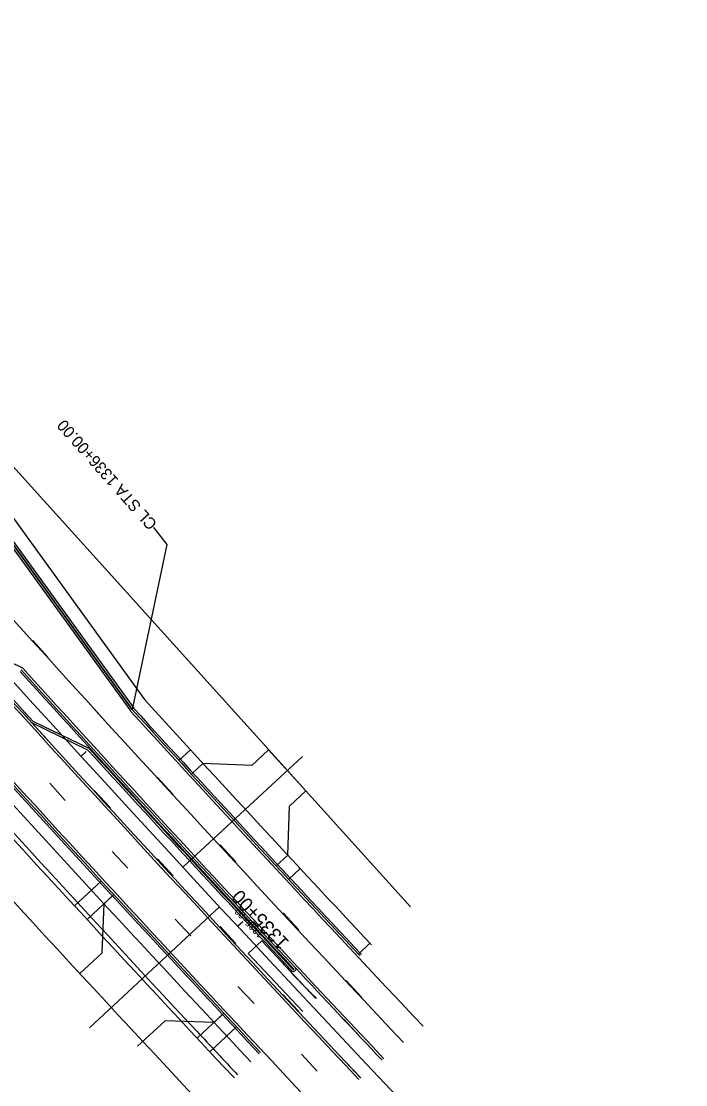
# Model space of a CAD drawing. Extents: x 2252205 to 2259955, y 13788514 to 13798103.
# Drawn here: x 2256634 to 2256921.6, y 13791797 to 13792257 of the extents above; entities that cross this region are included whole.
import ezdxf

# ---------------------------------------------------------------- set-up
doc = ezdxf.new("R2010")
doc.units = 0
for name, color, linetype in [('D_RDWY_TRACK_P_AND_T', 7, 'Continuous'), ('GEOM_CENTERLINE_ALIGN', 7, 'Continuous'), ('GEOM_CENTERLINE_STA_100', 7, 'Continuous'), ('GEOM_CENTERLINE_STA_50', 7, 'Continuous'), ('ROAD_BIKE_SHARED_USE', 7, 'Continuous'), ('Road_Curb_Back', 7, 'Continuous'), ('Road_Curb_Face', 7, 'Continuous'), ('ROAD_DRIVEWAY_EP', 7, 'Continuous'), ('Road_EdgeOfPavementInside', 7, 'Continuous'), ('Road_EdgeOfPavementOutside', 7, 'Continuous'), ('ROAD_PAVMRK_Y_4IN_BRK', 7, 'Continuous'), ('ROAD_ROW_EXIST', 7, 'Continuous'), ('ROAD_ROW_PROPOSED', 7, 'Continuous'), ('ROAD_SCRATCH_DRIVE_CL', 7, 'Continuous'), ('ROAD_SCRATCH_EP_CONTROL', 7, 'Continuous'), ('Road_Sidewalk_Back', 7, 'Continuous'), ('TRAF_PAVMRK_W_4IN_BRK', 7, 'Continuous'), ('TRAF_PAVMRK_W_4IN_SLD', 7, 'Continuous'), ('TRAF_PAVMRK_Y_4IN_SLD', 7, 'Continuous')]:
    doc.layers.add(name, color=color, linetype=linetype)

msp = doc.modelspace()

# ---------------------------------------------------------------- linework, layer by layer
at = {"layer": 'D_RDWY_TRACK_P_AND_T'}
for points in [[(2256761.55, 13791834.26), (2256738.1, 13791859.22), (2256732.27, 13791853.75), (2256755.81, 13791828.68)], [(2256746.32, 13791850.48), (2256747, 13791849.75), (2256747.69, 13791849.01), (2256748.37, 13791848.28), (2256749.05, 13791847.55), (2256749.73, 13791846.81), (2256750.4, 13791846.08), (2256751.08, 13791845.35), (2256751.75, 13791844.63), (2256752.41, 13791843.91), (2256753.08, 13791843.19), (2256753.74, 13791842.48), (2256754.4, 13791841.78), (2256755.06, 13791841.08), (2256755.72, 13791840.39), (2256756.38, 13791839.7), (2256757.04, 13791839.03), (2256757.7, 13791838.37), (2256758.36, 13791837.71), (2256759.02, 13791837.07), (2256759.68, 13791836.44), (2256760.34, 13791835.82), (2256761, 13791835.22), (2256761.67, 13791834.62), (2256761.8, 13791834.5)]]:
    msp.add_lwpolyline(points, dxfattribs=at)
at = {"layer": 'GEOM_CENTERLINE_ALIGN'}
msp.add_arc((2265119, 13799669.27), 11459.16, 219.418553, 224.327385, dxfattribs=at)
at = {"layer": 'GEOM_CENTERLINE_STA_100'}
for p, q in [((2256659.87, 13791939.1), (2256662.09, 13791941.13)), ((2256727.65, 13791865.58), (2256729.85, 13791867.62))]:
    msp.add_line(p, q, dxfattribs=at)
at = {"layer": 'GEOM_CENTERLINE_STA_50'}
for p, q in [((2256659.87, 13791939.1), (2256660.98, 13791940.11)), ((2256727.65, 13791865.58), (2256728.75, 13791866.6))]:
    msp.add_line(p, q, dxfattribs=at)
at = {"layer": 'ROAD_BIKE_SHARED_USE'}
for p, q in [((2256657.07, 13791874.35), (2256668.66, 13791885.11)), ((2256662.52, 13791868.49), (2256674.1, 13791879.24)), ((2256710.13, 13791817.18), (2256721.74, 13791827.95)), ((2256715.58, 13791811.32), (2256727.18, 13791822.09))]:
    msp.add_line(p, q, dxfattribs=at)
for radius, start, end in [(11494.99, 220.925074, 223.155573), (11504.99, 220.928174, 223.15647)]:
    msp.add_arc((2265119, 13799669.27), radius, start, end, dxfattribs=at)
at = {"layer": 'Road_Curb_Back'}
for p, q in [((2256623.89, 13792041.13), (2256682.66, 13791959.87)), ((2256663.33, 13791942.48), (2256639.1, 13791954.21))]:
    msp.add_line(p, q, dxfattribs=at)
for centre, radius, start, end in [((2265119, 13799669.27), 11464.33, 220.621764, 222.296129), ((2265119, 13799669.27), 11489.99, 220.923263, 223.155124), ((2265119, 13799669.27), 11453.99, 222.197552, 223.071947), ((2265119, 13799669.27), 11428.33, 222.421868, 223.149555), ((2265119, 13799669.27), 11454.33, 222.421067, 223.071947), ((2256751.77, 13791847.04), 0.167, 223.222, 42.9219)]:
    msp.add_arc(centre, radius, start, end, dxfattribs=at)
at = {"layer": 'Road_Curb_Face'}
msp.add_line((2256623.24, 13792040.61), (2256682.02, 13791959.34), dxfattribs=at)
for radius, start, end in [(11489.16, 220.923263, 223.155049), (11429.16, 222.421868, 223.149631)]:
    msp.add_arc((2265119, 13799669.27), radius, start, end, dxfattribs=at)
at = {"layer": 'ROAD_DRIVEWAY_EP'}
for p, q in [((2256707.23, 13791941.91), (2256702.21, 13791937.27)), ((2256741.07, 13791941.87), (2256733.84, 13791935.18)), ((2256757.22, 13791924.12), (2256741.07, 13791941.87)), ((2256712.66, 13791936.03), (2256707.64, 13791931.39)), ((2256733.84, 13791935.18), (2256712.66, 13791936.03)), ((2256757.22, 13791924.12), (2256750.13, 13791917.56)), ((2256749.31, 13791896.38), (2256750.13, 13791917.56)), ((2256749.31, 13791896.38), (2256744.29, 13791891.74)), ((2256754.74, 13791890.5), (2256749.72, 13791885.86)), ((2256669.83, 13791875.28), (2256674.1, 13791879.24)), ((2256669.01, 13791854.05), (2256669.83, 13791875.28)), ((2256784.9, 13791858.2), (2256779.92, 13791853.51)), ((2256659.34, 13791845.08), (2256669.01, 13791854.05)), ((2256717.44, 13791823.97), (2256721.72, 13791827.94)), ((2256684.38, 13791813.74), (2256696.22, 13791824.73)), ((2256717.44, 13791823.97), (2256696.22, 13791824.73))]:
    msp.add_line(p, q, dxfattribs=at)
at = {"layer": 'Road_EdgeOfPavementInside'}
msp.add_line((2256662.82, 13791941.8), (2256638.6, 13791953.53), dxfattribs=at)
for centre, radius, start, end in [((2265119, 13799669.27), 11465.16, 220.621764, 222.296933), ((2265119, 13799669.27), 11453.16, 222.19675, 223.071947), ((2265119, 13799669.27), 11455.16, 222.421868, 223.071947), ((2256751.77, 13791847.04), 1, 223.222, 42.9219)]:
    msp.add_arc(centre, radius, start, end, dxfattribs=at)
at = {"layer": 'Road_EdgeOfPavementOutside'}
msp.add_line((2256682.02, 13791959.34), (2256623.24, 13792040.61), dxfattribs=at)
for radius, start, end in [(11489.16, 220.923263, 223.155049), (11429.16, 222.421868, 223.149631)]:
    msp.add_arc((2265119, 13799669.27), radius, start, end, dxfattribs=at)
at = {"layer": 'ROAD_PAVMRK_Y_4IN_BRK'}
for points in [[(2256638.6, 13791953.53), (2256645.39, 13791946.19)], [(2256665.76, 13791924.17), (2256665.77, 13791924.16)], [(2256665.77, 13791924.16), (2256672.56, 13791916.82)], [(2256692.93, 13791894.8), (2256692.94, 13791894.79)], [(2256692.94, 13791894.79), (2256699.73, 13791887.45)], [(2256720.11, 13791865.43), (2256720.11, 13791865.42)], [(2256720.11, 13791865.42), (2256726.9, 13791858.08)], [(2256752.88, 13791847.32), (2256752.5, 13791847.72)], [(2256752.89, 13791847.31), (2256752.88, 13791847.32)], [(2256747.28, 13791836.06), (2256747.28, 13791836.05)], [(2256747.28, 13791836.05), (2256754.08, 13791828.71)], [(2256780.31, 13791818.18), (2256773.46, 13791825.47)], [(2256780.32, 13791818.18), (2256780.31, 13791818.18)], [(2256774.53, 13791806.77), (2256774.53, 13791806.76)], [(2256774.53, 13791806.76), (2256780.93, 13791800.01)]]:
    msp.add_lwpolyline(points, dxfattribs=at)
for radius, start, end in [(11465.16, 222.296933, 223.343138), (11453.16, 223.071933, 223.347169)]:
    msp.add_arc((2265119, 13799669.27), radius, start, end, dxfattribs=at)
at = {"layer": 'ROAD_ROW_EXIST'}
msp.add_line((2256429.73, 13792286.64), (2256802.4, 13791873.96), dxfattribs=at)
for start, end in [(220.760702, 223.023397), (223.023397, 223.152425)]:
    msp.add_arc((2265124.02, 13799672.91), 11509.2, start, end, dxfattribs=at)
at = {"layer": 'ROAD_ROW_PROPOSED'}
msp.add_arc((2265116.03, 13799666.59), 11519.16, 220.67779, 223.158467, dxfattribs=at)
at = {"layer": 'ROAD_SCRATCH_DRIVE_CL'}
for p, q in [((2256755.67, 13791939.02), (2256703.91, 13791891.18)), ((2256663.54, 13791821.69), (2256719.86, 13791873.96))]:
    msp.add_line(p, q, dxfattribs=at)
at = {"layer": 'ROAD_SCRATCH_EP_CONTROL'}
msp.add_lwpolyline([(2256691.25, 13792038.09), (2256697.06, 13792030.65), (2256682.02, 13791959.34)], dxfattribs=at)
at = {"layer": 'Road_Sidewalk_Back'}
msp.add_line((2256628.57, 13792044.9), (2256687.32, 13791963.66), dxfattribs=at)
msp.add_arc((2265119, 13799669.27), 11422.33, 222.423828, 223.14901, dxfattribs=at)
at = {"layer": 'TRAF_PAVMRK_W_4IN_BRK'}
for points in [[(2256645.7, 13791981.79), (2256639.02, 13791989.23)], [(2256645.7, 13791981.78), (2256645.7, 13791981.79)], [(2256672.45, 13791952.03), (2256671.66, 13791952.89), (2256665.75, 13791959.46)], [(2256672.46, 13791952.03), (2256672.45, 13791952.03)], [(2256699.68, 13791922.72), (2256692.87, 13791930.05)], [(2256646.34, 13791927.48), (2256646.35, 13791927.47)], [(2256646.35, 13791927.47), (2256653.05, 13791920.04)], [(2256699.69, 13791922.71), (2256699.68, 13791922.72)], [(2256726.91, 13791893.41), (2256720.1, 13791900.73)], [(2256673.35, 13791897.96), (2256673.36, 13791897.95)], [(2256673.36, 13791897.95), (2256680.18, 13791890.64)], [(2256726.92, 13791893.4), (2256726.91, 13791893.41)], [(2256700.64, 13791868.7), (2256700.65, 13791868.7)], [(2256700.65, 13791868.7), (2256707.47, 13791861.38)], [(2256754.14, 13791864.09), (2256747.33, 13791871.42)], [(2256754.15, 13791864.09), (2256754.14, 13791864.09)], [(2256781.37, 13791834.78), (2256774.56, 13791842.11)], [(2256727.94, 13791839.45), (2256727.94, 13791839.44)], [(2256727.94, 13791839.44), (2256734.77, 13791832.13)], [(2256781.38, 13791834.77), (2256781.37, 13791834.78)], [(2256755.23, 13791810.19), (2256755.24, 13791810.19)], [(2256755.24, 13791810.19), (2256762.06, 13791802.87)]]:
    msp.add_lwpolyline(points, dxfattribs=at)
msp.add_arc((2265119, 13799669.27), 11441.16, 220.646831, 223.351209, dxfattribs=at)
at = {"layer": 'TRAF_PAVMRK_W_4IN_SLD'}
msp.add_line((2256622.46, 13792039.98), (2256681.24, 13791958.71), dxfattribs=at)
for radius, start, end in [(11488.16, 220.923263, 223.335434), (11430.16, 222.421868, 223.35492)]:
    msp.add_arc((2265119, 13799669.27), radius, start, end, dxfattribs=at)
at = {"layer": 'TRAF_PAVMRK_Y_4IN_SLD'}
msp.add_line((2256634.62, 13791977.24), (2256610.47, 13791989.03), dxfattribs=at)
for radius, start, end in [(11466.16, 220.621747, 223.342802), (11452.16, 222.195787, 223.347506)]:
    msp.add_arc((2265119, 13799669.27), radius, start, end, dxfattribs=at)

# ---------------------------------------------------------------- texts
at = {"layer": 'GEOM_CENTERLINE_STA_100'}
msp.add_text('1335+00', height=6, rotation=132.9219, dxfattribs=at).set_placement((2256750.29, 13791858.85))
at = {"layer": 'GEOM_CENTERLINE_STA_50'}
msp.add_text('1335+00', height=3, rotation=132.9219, dxfattribs=at).set_placement((2256738.97, 13791862.21))
at = {"layer": 'ROAD_SCRATCH_EP_CONTROL'}
msp.add_text('CL STA 1336+00.00', height=5, rotation=131.5783, dxfattribs=at).set_placement((2256693.12, 13792039.75))

doc.saveas('drawing.dxf')
